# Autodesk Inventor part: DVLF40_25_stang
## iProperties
Created: 2010-03
Part Number: DVLF40_25_stang
Document SubType Name: Modeling
Designer: TB
Mass: 123.705 g
Surface Area: 203.11 cm^2
Volume: 123.705 cm^3
Density: 1 g/cm^3
Author: TB
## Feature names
1. Revolution1
2. Fillet1
3. Revolution2
